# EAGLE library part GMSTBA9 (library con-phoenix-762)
PHOENIX
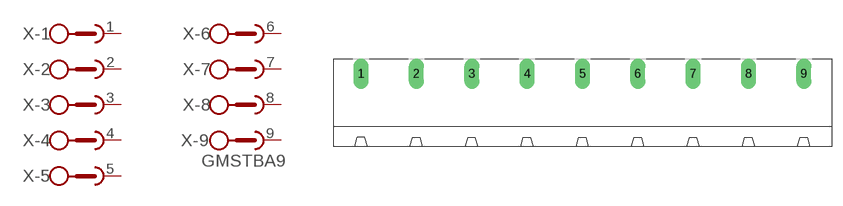
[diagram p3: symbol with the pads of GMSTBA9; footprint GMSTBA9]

Designator prefix X; gates -1=SKB -2=SKB -3=SKB -4=SKB -5=SKB -6=SKB -7=SKB -8=SKB -9=SKBV

## GMSTBA9 (MF: FARNELL; MPN: 1757310; OC_FARNELL: 3705237; OC_NEWARK: 71C4167)  [GMSTBA9]
1  -1:1  pas
2  -2:1  pas
3  -3:1  pas
4  -4:1  pas
5  -5:1  pas
6  -6:1  pas
7  -7:1  pas
8  -8:1  pas
9  -9:1  pas

## Footprint GMSTBA9 (pad centres in mm)
PHOENIX
drill 1.397 long: 1 -30.48,5.08; 2 -22.86,5.08; 3 -15.24,5.08; 4 -7.62,5.08; 5 0,5.08; 6 7.62,5.08; 7 15.24,5.08; 8 22.86,5.08; 9 30.48,5.08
